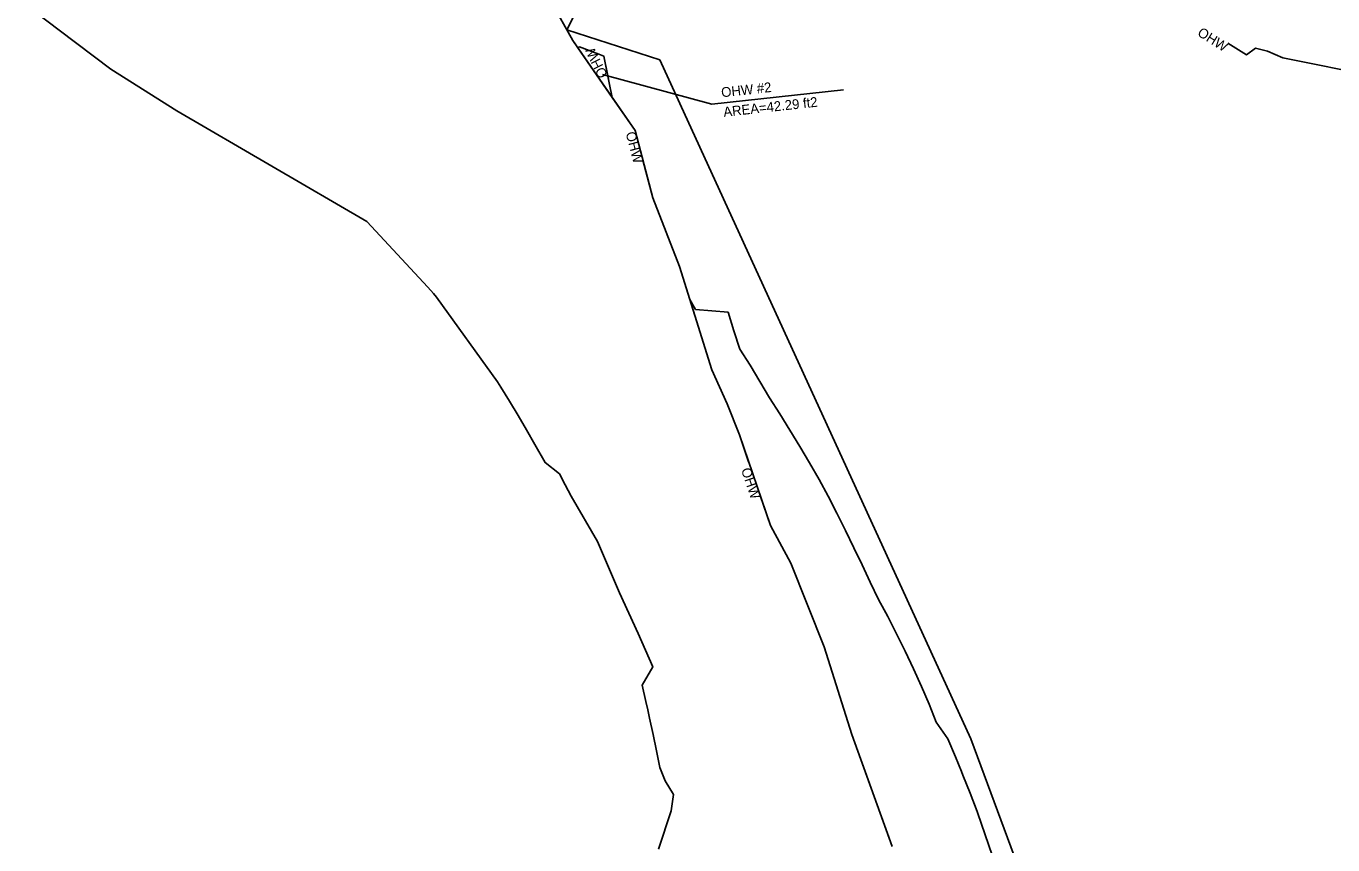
# Model space of a CAD drawing. Extents: x 1509537 to 1510685, y 401169 to 402194.
# Drawn here: x 1509560.8 to 1509932.9, y 401735.7 to 401968.9 of the extents above; entities that cross this region are included whole.
import ezdxf

# ---------------------------------------------------------------- set-up
doc = ezdxf.new("R2010")
doc.units = 0
for name, color, linetype in [('LAWE', 7, 'Continuous'), ('LAWE_P', 7, 'Continuous'), ('LAWE_P_T', 7, 'Continuous'), ('Level 6', 7, 'Continuous'), ('Level 9', 7, 'Continuous')]:
    doc.layers.add(name, color=color, linetype=linetype)

msp = doc.modelspace()

# ---------------------------------------------------------------- linework, layer by layer
at = {"layer": 'LAWE'}
for points in [[(1509733.33, 401940.36), (1509716.46, 401964.75), (1509704.07, 401986.85), (1509702.4, 401990.32), (1509683.49, 402022.15)], [(1509902.92, 401964.05), (1509908.24, 401960.7), (1509910.79, 401962.61), (1509914.24, 401961.76), (1509918.65, 401959.85), (1509945.07, 401954.56), (1509946.65, 401955.7), (1509949.25, 401954.95), (1509967.25, 401952.86), (1509969.07, 401952.46), (1509975.16, 401952.34)], [(1509766.51, 401844.78), (1509763.89, 401852.43), (1509760.37, 401861.31), (1509756.06, 401871.01), (1509746.78, 401900.45), (1509739.21, 401919.95), (1509736.39, 401930.7)], [(1509806.89, 401736.54), (1509795.89, 401767.18), (1509787.98, 401792.07), (1509778.47, 401815.96), (1509772.7, 401826.65), (1509769.78, 401835.2)]]:
    msp.add_lwpolyline(points, dxfattribs=at)
at = {"layer": 'LAWE_P'}
for p, q in [((1509718.34, 401962.97), (1509717.88, 401962.7)), ((1509717.88, 401962.7), (1509727.68, 401948.52)), ((1509727.68, 401948.52), (1509726.92, 401952.26)), ((1509751.37, 401888.16), (1509749.75, 401891.04)), ((1509760.68, 401887.41), (1509751.37, 401888.16)), ((1509762.31, 401882.1), (1509760.68, 401887.41)), ((1509764.02, 401876.86), (1509762.31, 401882.1)), ((1509766.92, 401872.3), (1509764.02, 401876.86)), ((1509769.71, 401867.67), (1509766.92, 401872.3)), ((1509778.25, 401853.82), (1509775.37, 401858.43)), ((1509781.08, 401849.17), (1509778.25, 401853.82)), ((1509789.17, 401834.98), (1509786.6, 401839.77)), ((1509791.65, 401830.13), (1509789.17, 401834.98)), ((1509794.06, 401825.24), (1509791.65, 401830.13)), ((1509803.52, 401805.56), (1509801.14, 401810.49)), ((1509806.1, 401800.7), (1509803.52, 401805.56)), ((1509807.37, 401798.25), (1509806.1, 401800.7)), ((1509808.62, 401795.79), (1509807.37, 401798.25)), ((1509815.72, 401780.84), (1509813.43, 401785.86)), ((1509817.93, 401775.77), (1509815.72, 401780.84)), ((1509836.93, 401729.78), (1509831.74, 401744.61))]:
    msp.add_line(p, q, dxfattribs=at)
for points in [[(1509725.23, 401960.35), (1509723.86, 401960.9), (1509718.34, 401962.97)], [(1509726.92, 401952.26), (1509726.41, 401954.71), (1509725.23, 401960.35)], [(1509749.75, 401891.04), (1509756.06, 401871.01), (1509760.37, 401861.31), (1509763.89, 401852.43), (1509772.7, 401826.65), (1509778.47, 401815.96), (1509787.98, 401792.07), (1509795.89, 401767.18), (1509807.37, 401735.22)], [(1509775.37, 401858.43), (1509772.45, 401863), (1509769.71, 401867.67)], [(1509786.6, 401839.77), (1509783.87, 401844.49), (1509781.08, 401849.17)], [(1509801.14, 401810.49), (1509798.81, 401815.43), (1509796.43, 401820.33), (1509794.06, 401825.24)], [(1509813.43, 401785.86), (1509811.07, 401790.85), (1509808.62, 401795.79)], [(1509831.74, 401744.61), (1509831.54, 401745.17), (1509829.56, 401750.39), (1509827.52, 401755.58), (1509827.11, 401756.62), (1509825.42, 401760.74), (1509823.26, 401765.87), (1509819.93, 401770.64), (1509817.93, 401775.77)]]:
    msp.add_lwpolyline(points, dxfattribs=at)
at = {"layer": 'LAWE_P_T'}
msp.add_lwpolyline([(1509724.88, 401955.12), (1509756.05, 401946.67), (1509793.51, 401950.76)], dxfattribs=at)
at = {"layer": 'Level 6'}
for p, q in [((1509717.88, 401962.7), (1509718.34, 401962.97)), ((1509726.92, 401952.26), (1509727.68, 401948.52)), ((1509749.75, 401891.04), (1509751.37, 401888.16)), ((1509751.37, 401888.16), (1509760.68, 401887.41)), ((1509760.68, 401887.41), (1509762.31, 401882.1)), ((1509762.31, 401882.1), (1509764.02, 401876.86)), ((1509775.37, 401858.43), (1509778.25, 401853.82)), ((1509778.25, 401853.82), (1509781.08, 401849.17)), ((1509786.6, 401839.77), (1509789.17, 401834.98)), ((1509789.17, 401834.98), (1509791.65, 401830.13)), ((1509796.43, 401820.33), (1509798.81, 401815.43)), ((1509798.81, 401815.43), (1509801.14, 401810.49)), ((1509801.14, 401810.49), (1509803.52, 401805.56)), ((1509803.52, 401805.56), (1509806.1, 401800.7)), ((1509806.1, 401800.7), (1509807.37, 401798.25)), ((1509807.37, 401798.25), (1509808.62, 401795.79)), ((1509808.62, 401795.79), (1509811.07, 401790.85)), ((1509811.07, 401790.85), (1509813.43, 401785.86)), ((1509813.43, 401785.86), (1509815.72, 401780.84)), ((1509815.72, 401780.84), (1509817.93, 401775.77)), ((1509823.26, 401765.87), (1509825.42, 401760.74)), ((1509827.52, 401755.58), (1509829.56, 401750.39)), ((1509829.56, 401750.39), (1509831.54, 401745.17)), ((1509831.54, 401745.17), (1509831.74, 401744.61))]:
    msp.add_line(p, q, dxfattribs=at)
for points in [[(1509875.57, 401568.19), (1509876.61, 401577.47), (1509866.1, 401667.73), (1509829.75, 401765.91), (1509741.2, 401959.3), (1509714.74, 401967.81)], [(1509714.74, 401967.81), (1509716.46, 401964.75), (1509717.88, 401962.7)], [(1509718.34, 401962.97), (1509723.86, 401960.9), (1509725.23, 401960.35), (1509726.92, 401952.26)], [(1509727.68, 401948.52), (1509734.18, 401939.14), (1509739.21, 401919.95), (1509746.78, 401900.45), (1509749.75, 401891.04)], [(1509764.02, 401876.86), (1509766.92, 401872.3), (1509769.71, 401867.67), (1509772.45, 401863), (1509775.37, 401858.43)], [(1509781.08, 401849.17), (1509783.87, 401844.49), (1509786.6, 401839.77)], [(1509791.65, 401830.13), (1509794.06, 401825.24), (1509796.43, 401820.33)], [(1509817.93, 401775.77), (1509819.93, 401770.64), (1509823.26, 401765.87)], [(1509825.42, 401760.74), (1509827.11, 401756.62), (1509827.52, 401755.58)], [(1509831.74, 401744.61), (1509836.93, 401729.78), (1509836.94, 401729.77)]]:
    msp.add_lwpolyline(points, dxfattribs=at)
at = {"layer": 'Level 9'}
for p, q in [((1509560.78, 401974.8), (1509570.18, 401967.69)), ((1509714.74, 401967.81), (1509716.67, 401971.54))]:
    msp.add_line(p, q, dxfattribs=at)
for points in [[(1509570.18, 401967.69), (1509584.86, 401956.59), (1509603.66, 401944.71), (1509657.75, 401913.27), (1509675.11, 401894.56), (1509676.78, 401892.7), (1509677.61, 401891.71), (1509694.97, 401867.56), (1509695.9, 401866.09), (1509698.4, 401862.04), (1509700.86, 401857.97), (1509703.27, 401853.88), (1509705.65, 401849.76), (1509708.57, 401844.58), (1509712.6, 401841.36), (1509714.3, 401838.21), (1509715.96, 401835.04), (1509723.5, 401822.07), (1509729.77, 401807.48), (1509735.09, 401795.93), (1509739.22, 401786.4), (1509736.22, 401781.21), (1509737.27, 401776.51), (1509737.78, 401774.17), (1509738.29, 401771.83), (1509739.29, 401767.14), (1509740.27, 401762.45), (1509741.23, 401757.78), (1509742.69, 401753.9), (1509745.08, 401750.04), (1509744.47, 401745.41), (1509740.85, 401734.45)], [(1509875.57, 401568.19), (1509876.61, 401577.47), (1509866.1, 401667.73), (1509829.75, 401765.91), (1509741.2, 401959.3), (1509714.74, 401967.81)]]:
    msp.add_lwpolyline(points, dxfattribs=at)

# ---------------------------------------------------------------- texts
at = {"layer": 'LAWE'}
for rotation, p in [(327.7343, (1509894.06, 401966.34)), (284.7042, (1509731.47, 401938.42)), (288.8667, (1509764.31, 401842.55))]:
    msp.add_text('OHW', height=2.8, rotation=rotation, dxfattribs=at).set_placement(p)
at = {"layer": 'LAWE_P'}
msp.add_text('OHW', height=2.8, rotation=116.2215, dxfattribs=at).set_placement((1509726.45, 401954.9))
at = {"layer": 'LAWE_P_T'}
for s, p in [('OHW #2', (1509758.85, 401948.58)), ('AREA=42.29 ft2', (1509759.46, 401943.02))]:
    msp.add_text(s, height=2.8, rotation=6.2219, dxfattribs=at).set_placement(p)

doc.saveas('drawing.dxf')
